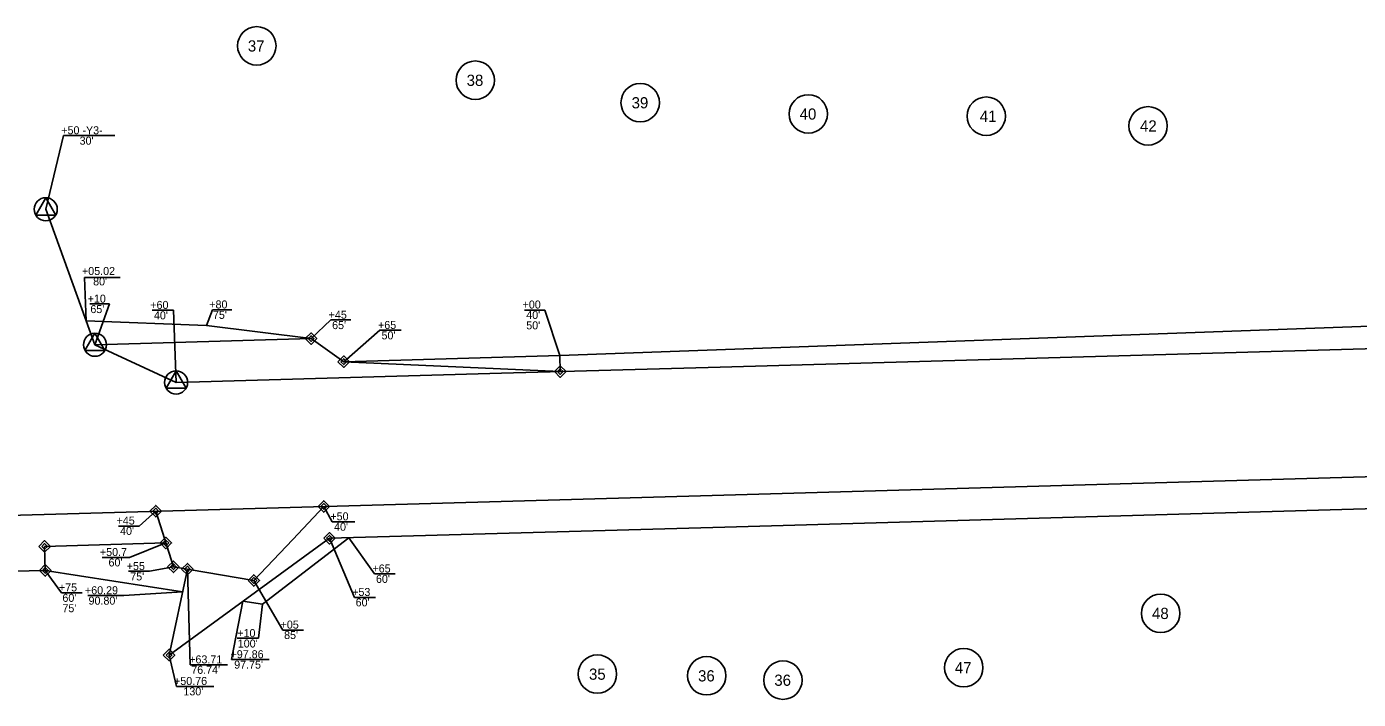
# Model space of a CAD drawing. Extents: x 1756120 to 1760612, y 736784 to 737319.
# Drawn here: x 1758949 to 1759780, y 736863 to 737283 of the extents above; entities that cross this region are included whole.
import ezdxf

# ---------------------------------------------------------------- set-up
doc = ezdxf.new("R2010")
doc.units = 0
for name, color, linetype in [('Old_Level_2', 7, 'Continuous'), ('Prop Easement Construction', 7, 'Continuous'), ('Prop Easement Construction Station Offsets', 7, 'Continuous'), ('Prop Easement Permanent Drainage', 7, 'Continuous'), ('Prop Easement Permanent Drainage Station Offsets', 7, 'Continuous'), ('Prop Easement Permanent Drainage Utility', 7, 'Continuous'), ('Prop Easement Permanent Drainage Utility Station Offsets', 7, 'Continuous'), ('Prop Easement Permanent Utility', 7, 'Continuous'), ('Prop Easement Permanent Utility Station Offsets', 7, 'Continuous'), ('Prop Easement Temporary Drainage', 7, 'Continuous'), ('Prop Easement Temporary Drainage Station Offsets', 7, 'Continuous'), ('Prop Parcel Number CELL', 7, 'Continuous'), ('Prop Parcel Number Text', 7, 'Continuous'), ('Prop ROW Marker CELL', 7, 'Continuous'), ('Prop ROW Permanent Easement CELL', 7, 'Continuous'), ('Prop ROW RW Lines', 7, 'Continuous'), ('Prop ROW Station Offsets', 7, 'Continuous')]:
    doc.layers.add(name, color=color, linetype=linetype)

msp = doc.modelspace()

# ---------------------------------------------------------------- linework, layer by layer
at = {"layer": 'Old_Level_2'}
msp.add_line((1759136.36, 736963.78), (1759136.86, 736963.28), dxfattribs=at)
at = {"layer": 'Prop Easement Construction'}
for p, q in [((1759281.67, 737077.95), (1759931.27, 737101.4)), ((1759096.01, 736922.62), (1759149.85, 736964.16)), ((1758960.35, 736943.77), (1759046.06, 736930.41)), ((1759083.81, 736924.52), (1759096.01, 736922.62))]:
    msp.add_line(p, q, dxfattribs=at)
at = {"layer": 'Prop Easement Construction Station Offsets'}
for p, q in [((1759149.85, 736964.16), (1759165.95, 736941.73)), ((1759178.8, 736941.73), (1759165.95, 736941.73)), ((1759046.06, 736930.41), (1759009.47, 736928.14)), ((1759009.47, 736928.14), (1758986.85, 736928.14)), ((1759083.81, 736924.52), (1759076.57, 736888.18)), ((1759096.01, 736922.62), (1759093.45, 736901.38)), ((1759093.45, 736901.38), (1759080.15, 736901.38)), ((1759100.14, 736888.18), (1759076.57, 736888.18))]:
    msp.add_line(p, q, dxfattribs=at)
at = {"layer": 'Prop Easement Permanent Drainage'}
for p, q in [((1758991.36, 737084.71), (1759126.31, 737088.54)), ((1759126.31, 737088.54), (1759146.73, 737074.12)), ((1759146.73, 737074.12), (1759281.96, 737067.95))]:
    msp.add_line(p, q, dxfattribs=at)
at = {"layer": 'Prop Easement Permanent Drainage Station Offsets'}
for p, q in [((1759138.75, 737100.2), (1759126.31, 737088.54)), ((1759138.75, 737100.2), (1759151.15, 737100.2)), ((1759169.28, 737093.81), (1759146.73, 737074.12)), ((1759169.28, 737093.81), (1759182.54, 737093.81))]:
    msp.add_line(p, q, dxfattribs=at)
at = {"layer": 'Prop Easement Permanent Drainage Utility'}
for p, q in [((1759040.32, 736946.05), (1759029.33, 736980.75)), ((1759114.86, 736963.17), (1759134.29, 736983.73)), ((1759090.58, 736937.47), (1759114.86, 736963.17)), ((1759040.32, 736946.05), (1759090.58, 736937.47))]:
    msp.add_line(p, q, dxfattribs=at)
at = {"layer": 'Prop Easement Permanent Drainage Utility Station Offsets'}
for p, q in [((1759018.98, 736971.41), (1759029.33, 736980.75)), ((1759139.52, 736974.08), (1759134.29, 736983.73)), ((1759139.52, 736974.08), (1759153.65, 736974.08)), ((1759006.15, 736971.41), (1759018.98, 736971.41)), ((1759012.39, 736943.34), (1759025.39, 736943.34)), ((1759025.39, 736943.34), (1759040.32, 736946.05)), ((1759108.63, 736906.45), (1759090.58, 736937.47)), ((1759108.63, 736906.45), (1759121.69, 736906.45))]:
    msp.add_line(p, q, dxfattribs=at)
at = {"layer": 'Prop Easement Permanent Utility'}
for p, q in [((1759384.75, 736970.83), (1760214.42, 736994.39)), ((1759037.64, 736890.95), (1759137.85, 736963.82)), ((1759137.85, 736963.82), (1759384.75, 736970.83)), ((1758959.93, 736958.77), (1759035.61, 736960.92)), ((1758959.93, 736958.77), (1758960.35, 736943.77)), ((1758940.36, 736943.21), (1758960.35, 736943.77)), ((1759049.08, 736944.55), (1759037.64, 736890.95))]:
    msp.add_line(p, q, dxfattribs=at)
at = {"layer": 'Prop Easement Permanent Utility Station Offsets'}
for p, q in [((1759153.56, 736926.93), (1759137.85, 736963.82)), ((1759012.9, 736951.83), (1759035.61, 736960.92)), ((1758995.82, 736951.83), (1759012.9, 736951.83)), ((1758970.4, 736929.77), (1758960.35, 736943.77)), ((1759050.78, 736884.82), (1759049.08, 736944.55)), ((1758970.4, 736929.77), (1758983.45, 736929.77)), ((1759153.56, 736926.93), (1759166.61, 736926.93)), ((1759153.56, 736926.93), (1759166.61, 736926.93)), ((1759042.31, 736871.36), (1759037.64, 736890.95)), ((1759050.78, 736884.82), (1759063.84, 736884.82)), ((1759050.78, 736884.82), (1759074.04, 736884.82)), ((1759042.31, 736871.36), (1759055.36, 736871.36)), ((1759042.31, 736871.36), (1759065.57, 736871.36))]:
    msp.add_line(p, q, dxfattribs=at)
at = {"layer": 'Prop Easement Temporary Drainage'}
for p, q in [((1758985.96, 737099.56), (1759061.05, 737096.69)), ((1759061.05, 737096.69), (1759126.31, 737088.54)), ((1759146.73, 737074.12), (1759281.67, 737077.95)), ((1759281.67, 737077.95), (1759281.96, 737067.95))]:
    msp.add_line(p, q, dxfattribs=at)
at = {"layer": 'Prop Easement Temporary Drainage Station Offsets'}
for p, q in [((1758984.77, 737126.69), (1758985.96, 737099.56)), ((1758984.77, 737126.69), (1759007.03, 737126.69)), ((1759064.87, 737106.6), (1759061.05, 737096.69)), ((1759064.87, 737106.6), (1759076.89, 737106.6)), ((1759272.33, 737106.22), (1759259.62, 737106.22)), ((1759272.33, 737106.22), (1759281.67, 737077.95))]:
    msp.add_line(p, q, dxfattribs=at)
at = {"layer": 'Prop Parcel Number CELL'}
for centre in [(1759092.43, 737271.37), (1759228.89, 737249.91), (1759331.9, 737235.88), (1759436.88, 737228.85), (1759548.04, 737227.45), (1759649.11, 737221.4), (1759656.96, 736916.96), (1759305.18, 736879.05), (1759373.44, 736877.99), (1759534, 736883.04), (1759421.05, 736875.25)]:
    msp.add_circle(centre, 12, dxfattribs=at)
at = {"layer": 'Prop ROW Marker CELL'}
for p, q in [((1758960.6, 737169.33), (1758960.6, 737169.33)), ((1759126.31, 737088.54), (1759126.31, 737088.54)), ((1758991.36, 737084.71), (1758991.36, 737084.71)), ((1759146.73, 737074.12), (1759146.73, 737074.12)), ((1759281.96, 737067.95), (1759281.96, 737067.95)), ((1759042.05, 737061.14), (1759042.05, 737061.14)), ((1759029.33, 736980.75), (1759029.33, 736980.75)), ((1759134.29, 736983.73), (1759134.29, 736983.73)), ((1759137.85, 736963.82), (1759137.85, 736963.82)), ((1758959.93, 736958.77), (1758959.93, 736958.77)), ((1759035.61, 736960.92), (1759035.61, 736960.92)), ((1758960.35, 736943.77), (1758960.35, 736943.77)), ((1759040.32, 736946.05), (1759040.32, 736946.05)), ((1759049.08, 736944.55), (1759049.08, 736944.55)), ((1759090.58, 736937.47), (1759090.58, 736937.47)), ((1759037.64, 736890.95), (1759037.64, 736890.95))]:
    msp.add_line(p, q, dxfattribs=at)
for points in [[(1758954.35, 737165.73), (1758960.6, 737176.53), (1758966.85, 737165.73)], [(1758985.11, 737081.11), (1758991.36, 737091.91), (1758997.61, 737081.11)], [(1759035.8, 737057.54), (1759042.05, 737068.34), (1759048.3, 737057.54)]]:
    msp.add_lwpolyline(points, close=True, dxfattribs=at)
for centre in [(1758960.6, 737169.33), (1758991.36, 737084.71), (1759042.05, 737061.14)]:
    msp.add_circle(centre, 7.2, dxfattribs=at)
at = {"layer": 'Prop ROW Permanent Easement CELL'}
for points in [[(1759122.71, 737088.54), (1759126.31, 737092.14), (1759129.91, 737088.54), (1759126.31, 737084.94)], [(1759124.51, 737088.54), (1759126.31, 737090.34), (1759128.11, 737088.54), (1759126.31, 737086.74)], [(1759143.13, 737074.12), (1759146.73, 737077.72), (1759150.33, 737074.12), (1759146.73, 737070.52)], [(1759144.93, 737074.12), (1759146.73, 737075.92), (1759148.53, 737074.12), (1759146.73, 737072.32)], [(1759278.36, 737067.95), (1759281.96, 737071.55), (1759285.56, 737067.95), (1759281.96, 737064.35)], [(1759280.16, 737067.95), (1759281.96, 737069.75), (1759283.76, 737067.95), (1759281.96, 737066.15)], [(1759025.73, 736980.75), (1759029.33, 736984.35), (1759032.93, 736980.75), (1759029.33, 736977.15)], [(1759027.53, 736980.75), (1759029.33, 736982.55), (1759031.13, 736980.75), (1759029.33, 736978.95)], [(1759130.69, 736983.73), (1759134.29, 736987.33), (1759137.89, 736983.73), (1759134.29, 736980.13)], [(1759132.49, 736983.73), (1759134.29, 736985.53), (1759136.09, 736983.73), (1759134.29, 736981.93)], [(1759032.01, 736960.92), (1759035.61, 736964.52), (1759039.21, 736960.92), (1759035.61, 736957.32)], [(1759134.26, 736963.82), (1759137.86, 736967.42), (1759141.45, 736963.82), (1759137.86, 736960.22)], [(1759136.06, 736963.82), (1759137.86, 736965.62), (1759139.65, 736963.82), (1759137.86, 736962.02)], [(1758956.33, 736958.77), (1758959.93, 736962.37), (1758963.53, 736958.77), (1758959.93, 736955.17)], [(1758958.13, 736958.77), (1758959.93, 736960.57), (1758961.73, 736958.77), (1758959.93, 736956.97)], [(1759033.81, 736960.92), (1759035.61, 736962.72), (1759037.41, 736960.92), (1759035.61, 736959.12)], [(1758956.75, 736943.77), (1758960.35, 736947.37), (1758963.95, 736943.77), (1758960.35, 736940.17)], [(1759036.72, 736946.05), (1759040.32, 736949.65), (1759043.92, 736946.05), (1759040.32, 736942.45)], [(1759038.52, 736946.05), (1759040.32, 736947.85), (1759042.12, 736946.05), (1759040.32, 736944.25)], [(1759045.48, 736944.55), (1759049.08, 736948.15), (1759052.68, 736944.55), (1759049.08, 736940.95)], [(1758958.55, 736943.77), (1758960.35, 736945.57), (1758962.15, 736943.77), (1758960.35, 736941.97)], [(1759047.28, 736944.55), (1759049.08, 736946.35), (1759050.88, 736944.55), (1759049.08, 736942.75)], [(1759086.98, 736937.47), (1759090.58, 736941.07), (1759094.18, 736937.47), (1759090.58, 736933.87)], [(1759088.78, 736937.47), (1759090.58, 736939.27), (1759092.38, 736937.47), (1759090.58, 736935.67)], [(1759034.04, 736890.95), (1759037.64, 736894.55), (1759041.24, 736890.95), (1759037.64, 736887.35)], [(1759035.84, 736890.95), (1759037.64, 736892.75), (1759039.44, 736890.95), (1759037.64, 736889.15)]]:
    msp.add_lwpolyline(points, close=True, dxfattribs=at)
at = {"layer": 'Prop ROW RW Lines'}
for p, q in [((1758960.6, 737169.33), (1758991.36, 737084.71)), ((1759381.91, 737070.79), (1760206.58, 737094.21)), ((1758991.36, 737084.71), (1759042.05, 737061.14)), ((1759042.05, 737061.14), (1759245.3, 737066.91)), ((1759245.3, 737066.91), (1759381.91, 737070.79)), ((1759384.18, 736990.82), (1760223.85, 737014.67)), ((1758084.71, 736953.92), (1759384.18, 736990.82))]:
    msp.add_line(p, q, dxfattribs=at)
at = {"layer": 'Prop ROW Station Offsets'}
for p, q in [((1759003.87, 737215.4), (1758971.65, 737215.4)), ((1758988.19, 737110.19), (1759000.45, 737110.19)), ((1759000.45, 737110.19), (1758991.36, 737084.71)), ((1759040.38, 737106.24), (1759027.08, 737106.24))]:
    msp.add_line(p, q, dxfattribs=at)
for points in [[(1758971.65, 737215.4), (1758960.6, 737169.33)], [(1759040.38, 737106.24), (1759042.05, 737061.14)]]:
    msp.add_lwpolyline(points, dxfattribs=at)

# ---------------------------------------------------------------- texts
at = {"layer": 'Prop Easement Construction Station Offsets'}
for s, p in [('+65', (1759164.68, 736942.48)), ("60'", (1759166.87, 736935.98)), ('+60.29', (1758985.11, 736928.89)), ("90.80'", (1758987.35, 736922.39)), ('+10', (1759080.25, 736902.13)), ("100'", (1759080.55, 736895.63)), ('+97.86', (1759076.04, 736888.93)), ("97.75'", (1759078.31, 736882.43))]:
    msp.add_text(s, height=5, dxfattribs=at).set_placement(p)
at = {"layer": 'Prop Easement Permanent Drainage Station Offsets'}
for s, p in [('+45', (1759137.3, 737100.97)), ("65'", (1759139.48, 737094.47)), ('+65', (1759168.14, 737094.56)), ("50'", (1759170.32, 737088.06))]:
    msp.add_text(s, height=5, rotation=0.00001, dxfattribs=at).set_placement(p)
at = {"layer": 'Prop Easement Permanent Drainage Utility Station Offsets'}
for s, p in [('+50', (1759138.41, 736975.05)), ('+45', (1759004.86, 736972.43)), ("40'", (1759140.7, 736968.55)), ("40'", (1759007.05, 736965.93)), ('+55', (1759011.21, 736944.02)), ("75'", (1759013.39, 736937.52)), ('+05', (1759107.3, 736907.43)), ("85'", (1759109.49, 736900.93))]:
    msp.add_text(s, height=5, rotation=0.00001, dxfattribs=at).set_placement(p)
at = {"layer": 'Prop Easement Permanent Utility Station Offsets'}
for s, p in [('+50.7', (1758994.44, 736952.76)), ("60'", (1758999.81, 736946.26)), ('+75', (1758968.84, 736930.65)), ('+53', (1759152.01, 736927.82)), ("60'", (1758971.03, 736924.15)), ("75'", (1758971.03, 736917.65)), ("60'", (1759154.18, 736921.32)), ('+63.71', (1759050.21, 736885.7)), ("76.74'", (1759051.5, 736879.2)), ('+50.76', (1759040.76, 736872.24)), ("130'", (1759046.59, 736865.74))]:
    msp.add_text(s, height=5, rotation=0.00001, dxfattribs=at).set_placement(p)
at = {"layer": 'Prop Easement Temporary Drainage Station Offsets'}
for s, p in [('+05.02', (1758983.25, 737128.26)), ("80'", (1758990.2, 737121.76)), ('+80', (1759062.75, 737107.37)), ("75'", (1759065.04, 737100.87))]:
    msp.add_text(s, height=5, rotation=0.00001, dxfattribs=at).set_placement(p)
for s, p in [('+00', (1759258.44, 737107.32)), ("40'", (1759260.73, 737100.82)), ("50'", (1759260.73, 737094.32))]:
    msp.add_text(s, height=5, dxfattribs=at).set_placement(p)
at = {"layer": 'Prop Parcel Number Text'}
for s, p in [('37', (1759086.86, 737267.81)), ('38', (1759223.49, 737246.36)), ('39', (1759326.54, 737232.33)), ('40', (1759431.47, 737225.29)), ('41', (1759544.01, 737223.89)), ('42', (1759644.08, 737217.85)), ('48', (1759651.56, 736913.41)), ('35', (1759299.91, 736875.5)), ('36', (1759368.04, 736874.44)), ('47', (1759528.42, 736879.48)), ('36', (1759415.66, 736871.7))]:
    msp.add_text(s, height=7, rotation=0.00001, dxfattribs=at).set_placement(p)
at = {"layer": 'Prop ROW Station Offsets'}
for s, p in [('+50 -Y3-', (1758970.32, 737216.15)), ("30'", (1758981.77, 737209.65)), ('+60', (1759025.92, 737107.07)), ("40'", (1759028.2, 737100.57))]:
    msp.add_text(s, height=5, dxfattribs=at).set_placement(p)
for s, p in [('+10', (1758986.8, 737110.98)), ("65'", (1758988.49, 737104.48))]:
    msp.add_text(s, height=5, rotation=0.00001, dxfattribs=at).set_placement(p)

doc.saveas('drawing.dxf')
